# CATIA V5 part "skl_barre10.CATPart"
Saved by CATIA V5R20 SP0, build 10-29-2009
Part number: skl_barre10
Publications: "Barre_10", "Axe_Pivot_b10b9", "Axe_Pivot_b10b11"
Bounding box of the stored display mesh (mm): x 0 to 394.671, y -58.143 to 313.648, z 0 to 20
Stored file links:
  C:\Users\Matthieu\Desktop\IFMA\Cours 2A\Thinkmotion\skl_barre10.CATPart
  C:\Users\Matthieu\Desktop\IFMA\Cours 2A\Thinkmotion\skl_IAO_bis.CATProduct
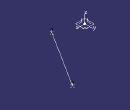
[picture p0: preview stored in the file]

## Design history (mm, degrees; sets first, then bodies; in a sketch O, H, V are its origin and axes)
AxisSystem1: origin (0, 0, 0), X (1, 0, 0), Y (0, 1, 0), Z (0, 0, 1)
Set1
  Point1 "Point.H": linked copy from another document
  Point2 "Point.K": linked copy from another document
  Plane1 "Plan_Ref": linked copy from another document
Body1 (main body)
  Line1 "Barre_10": type PtPt, FirstPoint Point1, SecondPoint Point2
  Line2 "Axe_Pivot_b10b9": type Normal, RefPoint Point1, RefSkin Plane1, Start 0, End 20
  Line3 "Axe_Pivot_b10b11": type Normal, RefPoint Point2, RefSkin Plane1, Start 0, End 20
